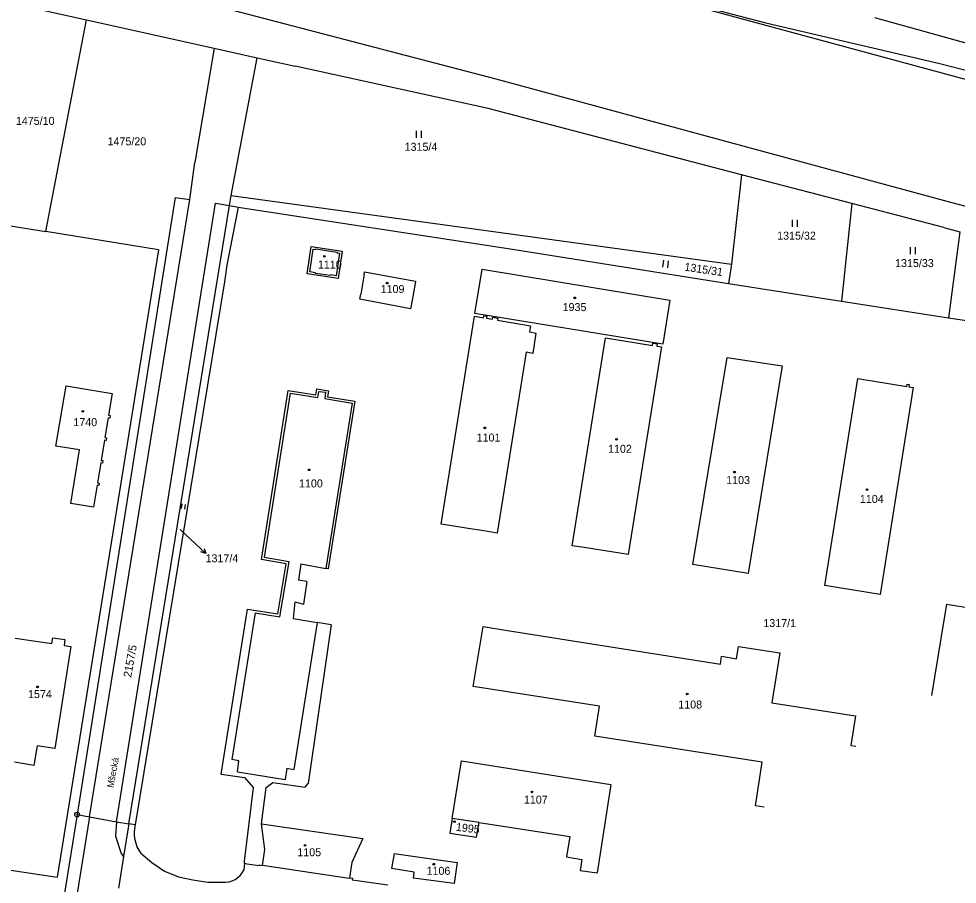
# Model space of a CAD drawing. Extents: x -779596 to -776743, y -1030330 to -1024513.
# Drawn here: x -778728.9 to -778529.6, y -1029872.1 to -1029688.2 of the extents above; entities that cross this region are included whole.
import ezdxf

# ---------------------------------------------------------------- set-up
doc = ezdxf.new("R2010")
doc.units = 0
for name, color, linetype in [('hranice parcel', 7, 'Continuous'), ('hranice vnitřní', 7, 'Continuous'), ('kultura', 7, 'Continuous'), ('Kód', 7, 'Continuous'), ('názvosloví', 7, 'Continuous'), ('č_ parcel šipka', 7, 'Continuous'), ('č_pacel stav_', 7, 'Continuous'), ('č_parcel poz_', 7, 'Continuous')]:
    doc.layers.add(name, color=color, linetype=linetype)

msp = doc.modelspace()

# ---------------------------------------------------------------- linework, layer by layer
at = {"layer": 'hranice parcel'}
for points in [[(-778728.82, -1029685.3), (-778714.47, -1029688.49)], [(-778723.12, -1029733.47), (-778714.47, -1029688.49)], [(-778714.47, -1029688.49), (-778687.4, -1029694.47)], [(-778547.21, -1029688.01), (-778525.04, -1029694.15)], [(-778687.4, -1029694.47), (-778691.45, -1029718.81)], [(-778687.4, -1029694.47), (-778678.25, -1029696.53)], [(-778683.75, -1029725.76), (-778678.25, -1029696.53)], [(-778678.25, -1029696.53), (-778670.2, -1029698.32)], [(-778629.23, -1029707.34), (-778670.2, -1029698.32)], [(-778575.41, -1029721.37), (-778629.23, -1029707.34)], [(-778692.58, -1029726.61), (-778691.45, -1029718.81)], [(-778575.41, -1029721.37), (-778577.55, -1029740.4)], [(-778552.03, -1029727.46), (-778575.41, -1029721.37)], [(-778695.65, -1029726.2), (-778716.48, -1029857.29)], [(-778695.65, -1029726.2), (-778692.58, -1029726.61)], [(-778684.15, -1029727.9), (-778683.75, -1029725.76)], [(-778683.75, -1029725.76), (-778577.55, -1029740.4)], [(-778705.49, -1029859.24), (-778684.15, -1029727.9)], [(-778682.29, -1029728.26), (-778684.67, -1029740.58)], [(-778684.15, -1029727.9), (-778682.29, -1029728.26)], [(-778682.29, -1029728.26), (-778624.95, -1029737.08)], [(-778552.03, -1029727.46), (-778554.23, -1029748.22)], [(-778532.46, -1029732.56), (-778552.03, -1029727.46)], [(-778739.16, -1029730.88), (-778723.12, -1029733.47)], [(-778699.18, -1029737.34), (-778723.12, -1029733.47)], [(-778532.46, -1029732.56), (-778529.06, -1029733.5)], [(-778529.06, -1029733.5), (-778531.48, -1029751.76)], [(-778699.18, -1029737.34), (-778720.7, -1029870.58)], [(-778667.67, -1029742.45), (-778666.78, -1029736.64)], [(-778666.78, -1029736.64), (-778660.19, -1029737.62)], [(-778660.19, -1029737.62), (-778661.03, -1029743.41)], [(-778624.95, -1029737.08), (-778585.37, -1029743.37)], [(-778577.55, -1029740.4), (-778578.22, -1029744.48)], [(-778684.67, -1029740.58), (-778685.17, -1029744.12)], [(-778661.03, -1029743.41), (-778667.67, -1029742.45)], [(-778655.57, -1029742.53), (-778655.48, -1029741.99)], [(-778655.48, -1029741.99), (-778644.64, -1029743.96)], [(-778632.01, -1029750.85), (-778630.51, -1029741.46)], [(-778630.51, -1029741.46), (-778590.64, -1029747.99)], [(-778685.17, -1029744.12), (-778704.18, -1029859.45)], [(-778655.57, -1029742.53), (-778656.27, -1029746.74)], [(-778644.64, -1029743.96), (-778644.74, -1029744.51)], [(-778585.37, -1029743.37), (-778578.22, -1029744.48)], [(-778578.22, -1029744.48), (-778554.23, -1029748.22)], [(-778644.74, -1029744.51), (-778645.48, -1029748.77)], [(-778656.45, -1029747.79), (-778656.27, -1029746.74)], [(-778645.67, -1029749.84), (-778656.45, -1029747.79)], [(-778590.64, -1029747.99), (-778592.14, -1029757.37)], [(-778554.23, -1029748.22), (-778531.48, -1029751.76)], [(-778645.48, -1029748.77), (-778645.67, -1029749.84)], [(-778639.2, -1029795.58), (-778632.11, -1029751.44)], [(-778632.11, -1029751.44), (-778630.17, -1029751.77)], [(-778592.14, -1029757.37), (-778632.01, -1029750.85)], [(-778630.17, -1029751.77), (-778630.1, -1029751.33)], [(-778630.1, -1029751.33), (-778629.51, -1029751.43)], [(-778629.51, -1029751.43), (-778629.58, -1029751.87)], [(-778629.58, -1029751.87), (-778628.28, -1029752.09)], [(-778628.28, -1029752.09), (-778628.21, -1029751.65)], [(-778628.21, -1029751.65), (-778627.13, -1029751.83)], [(-778627.13, -1029751.83), (-778627.2, -1029752.27)], [(-778627.2, -1029752.27), (-778620.25, -1029753.44)], [(-778531.48, -1029751.76), (-778515.73, -1029754.1)], [(-778620.25, -1029753.44), (-778620.46, -1029754.77)], [(-778620.46, -1029754.77), (-778619.06, -1029755)], [(-778619.06, -1029755), (-778619.76, -1029759.32)], [(-778611.37, -1029800.19), (-778604.27, -1029756.04)], [(-778604.27, -1029756.04), (-778594.31, -1029757.62)], [(-778592.41, -1029757.93), (-778599.46, -1029802.02)], [(-778594.31, -1029757.62), (-778594.24, -1029757.17)], [(-778594.24, -1029757.17), (-778593.31, -1029757.32)], [(-778593.31, -1029757.32), (-778593.38, -1029757.77)], [(-778593.38, -1029757.77), (-778592.41, -1029757.93)], [(-778621.15, -1029759.09), (-778627.27, -1029797.48)], [(-778619.76, -1029759.32), (-778621.15, -1029759.09)], [(-778585.79, -1029804.18), (-778578.5, -1029760.18)], [(-778578.5, -1029760.18), (-778566.79, -1029762)], [(-778566.79, -1029762), (-778574, -1029806.09)], [(-778721, -1029779.02), (-778718.79, -1029766.21)], [(-778718.79, -1029766.21), (-778709.02, -1029767.82)], [(-778557.75, -1029808.66), (-778550.73, -1029764.66)], [(-778550.73, -1029764.66), (-778540.36, -1029766.35)], [(-778540.36, -1029766.35), (-778540.28, -1029765.88)], [(-778540.28, -1029765.88), (-778539.84, -1029765.95)], [(-778539.84, -1029765.95), (-778539.92, -1029766.43)], [(-778709.02, -1029767.82), (-778709.78, -1029772.47)], [(-778677.35, -1029803.13), (-778671.68, -1029767.2)], [(-778671.68, -1029767.2), (-778665.8, -1029768.13)], [(-778665.8, -1029768.13), (-778665.6, -1029766.87)], [(-778665.6, -1029766.87), (-778663.13, -1029767.26)], [(-778663.13, -1029767.26), (-778663.33, -1029768.53)], [(-778538.98, -1029766.58), (-778545.96, -1029810.56)], [(-778539.92, -1029766.43), (-778538.98, -1029766.58)], [(-778663.33, -1029768.53), (-778657.52, -1029769.45)], [(-778657.52, -1029769.45), (-778663.16, -1029805.09)], [(-778709.87, -1029773.01), (-778710.56, -1029777.21)], [(-778709.52, -1029773.07), (-778709.87, -1029773.01)], [(-778709.78, -1029772.47), (-778709.44, -1029772.52)], [(-778709.44, -1029772.52), (-778709.52, -1029773.07)], [(-778710.65, -1029777.75), (-778711.35, -1029782.06)], [(-778710.3, -1029777.81), (-778710.65, -1029777.75)], [(-778710.56, -1029777.21), (-778710.21, -1029777.27)], [(-778710.21, -1029777.27), (-778710.3, -1029777.81)], [(-778715.97, -1029779.84), (-778721, -1029779.02)], [(-778717.82, -1029791.2), (-778715.97, -1029779.84)], [(-778711.35, -1029782.06), (-778711.01, -1029782.11)], [(-778711.01, -1029782.11), (-778711.1, -1029782.66)], [(-778711.44, -1029782.6), (-778712.13, -1029786.8)], [(-778711.1, -1029782.66), (-778711.44, -1029782.6)], [(-778712.22, -1029787.34), (-778712.98, -1029791.99)], [(-778711.87, -1029787.4), (-778712.22, -1029787.34)], [(-778712.13, -1029786.8), (-778711.78, -1029786.86)], [(-778711.78, -1029786.86), (-778711.87, -1029787.4)], [(-778712.98, -1029791.99), (-778717.82, -1029791.2)], [(-778632.57, -1029796.64), (-778639.2, -1029795.58)], [(-778630.54, -1029796.96), (-778632.57, -1029796.64)], [(-778627.27, -1029797.48), (-778630.54, -1029796.96)], [(-778608.84, -1029800.58), (-778611.37, -1029800.19)], [(-778599.46, -1029802.02), (-778608.84, -1029800.58)], [(-778672.06, -1029804.02), (-778677.35, -1029803.13)], [(-778673.87, -1029814.67), (-778672.06, -1029804.02)], [(-778668.97, -1029804.06), (-778669.5, -1029807.49)], [(-778668.97, -1029804.06), (-778663.65, -1029805.01)], [(-778574, -1029806.09), (-778585.79, -1029804.18)], [(-778663.16, -1029805.09), (-778663.65, -1029805.01)], [(-778667.68, -1029807.78), (-778669.5, -1029807.49)], [(-778667.68, -1029807.78), (-778668.39, -1029812.56)], [(-778545.96, -1029810.56), (-778557.75, -1029808.66)], [(-778670.26, -1029812.13), (-778670.62, -1029815.61)], [(-778670.26, -1029812.13), (-778668.39, -1029812.56)], [(-778685.9, -1029848.72), (-778680.28, -1029813.65)], [(-778680.28, -1029813.65), (-778673.87, -1029814.67)], [(-778531.93, -1029812.56), (-778533.12, -1029819.9)], [(-778531.93, -1029812.56), (-778510.985, -1029815.95)], [(-778670.62, -1029815.61), (-778665.53, -1029816.51)], [(-778662.52, -1029816.98), (-778667.44, -1029850.65)], [(-778662.52, -1029816.98), (-778665.53, -1029816.51)], [(-778632.41, -1029830.09), (-778630.3, -1029817.35)], [(-778630.3, -1029817.35), (-778625.11, -1029818.17)], [(-778625.11, -1029818.17), (-778579.91, -1029825.33)], [(-778729.63, -1029819.78), (-778721.82, -1029820.96)], [(-778721.82, -1029820.96), (-778721.64, -1029819.74)], [(-778721.64, -1029819.74), (-778719.06, -1029820.13)], [(-778719.06, -1029820.13), (-778719.24, -1029821.35)], [(-778533.12, -1029819.9), (-778535.077, -1029832.02)], [(-778717.81, -1029821.57), (-778721.22, -1029843.28)], [(-778719.24, -1029821.35), (-778717.81, -1029821.57)], [(-778576.46, -1029824.17), (-778576.09, -1029821.61)], [(-778576.09, -1029821.61), (-778567.32, -1029822.92)], [(-778579.91, -1029825.33), (-778579.69, -1029823.67)], [(-778579.69, -1029823.67), (-778576.46, -1029824.17)], [(-778567.32, -1029822.92), (-778568.98, -1029833.55)], [(-778605.58, -1029834.28), (-778632.41, -1029830.09)], [(-778568.98, -1029833.55), (-778551.21, -1029836.32)], [(-778606.56, -1029840.66), (-778605.58, -1029834.28)], [(-778551.21, -1029836.32), (-778552.19, -1029842.62)], [(-778571.01, -1029846.12), (-778606.56, -1029840.66)], [(-778724.99, -1029842.67), (-778725.66, -1029846.84)], [(-778721.22, -1029843.28), (-778724.99, -1029842.67)], [(-778552.19, -1029842.62), (-778551.186, -1029842.766)], [(-778636.83, -1029858.09), (-778634.86, -1029845.89)], [(-778634.86, -1029845.89), (-778603.18, -1029850.9)], [(-778725.66, -1029846.84), (-778729.79, -1029846.18)], [(-778572.46, -1029855.44), (-778571.01, -1029846.12)], [(-778685.9, -1029848.72), (-778680.96, -1029849.44)], [(-778680.96, -1029849.44), (-778679.05, -1029851.58)], [(-778680.92, -1029867.19), (-778679.05, -1029851.58)], [(-778677.34, -1029859.26), (-778676.33, -1029851.54)], [(-778676.33, -1029851.54), (-778674.91, -1029850.45)], [(-778674.91, -1029850.45), (-778668.03, -1029851.44)], [(-778668.03, -1029851.44), (-778667.44, -1029850.65)], [(-778603.18, -1029850.9), (-778606.06, -1029869.67)], [(-778570.603, -1029855.717), (-778572.46, -1029855.44)], [(-778716.48, -1029857.29), (-778719.14, -1029873.99)], [(-778716.48, -1029857.29), (-778713.86, -1029857.77)], [(-778713.86, -1029857.77), (-778708.13, -1029858.82)], [(-778708.13, -1029858.82), (-778705.49, -1029859.24)], [(-778705.49, -1029859.24), (-778706.61, -1029866.18)], [(-778704.18, -1029859.45), (-778705.49, -1029859.24)], [(-778676.6, -1029864.71), (-778677.34, -1029859.26)], [(-778677.34, -1029859.26), (-778655.83, -1029862.4)], [(-778636.83, -1029858.09), (-778637.34, -1029861.23)], [(-778631.15, -1029858.97), (-778636.83, -1029858.09)], [(-778631.66, -1029862.11), (-778631.15, -1029858.97)], [(-778631.15, -1029858.97), (-778611.85, -1029861.94)], [(-778637.34, -1029861.23), (-778631.66, -1029862.11)], [(-778611.85, -1029861.94), (-778612.55, -1029866.23)], [(-778655.83, -1029862.4), (-778658.18, -1029867.44)], [(-778702.97, -1029865.49), (-778700.58, -1029867.48)], [(-778677.15, -1029868.08), (-778676.6, -1029864.71)], [(-778649.2, -1029865.57), (-778649.74, -1029868.75)], [(-778649.2, -1029865.57), (-778635.77, -1029867.45)], [(-778747.94, -1029866.48), (-778720.7, -1029870.58)], [(-778706.61, -1029866.18), (-778707.7, -1029872.91)], [(-778700.58, -1029867.48), (-778697.96, -1029869.29)], [(-778680.96, -1029867.63), (-778681.09, -1029869.06)], [(-778680.96, -1029867.63), (-778680.92, -1029867.19)], [(-778680.96, -1029867.63), (-778680.39, -1029867.72)], [(-778680.39, -1029867.72), (-778678.86, -1029867.97)], [(-778678.86, -1029867.97), (-778677.85, -1029868.13)], [(-778677.85, -1029868.13), (-778677.83, -1029867.98)], [(-778677.83, -1029867.98), (-778677.15, -1029868.08)], [(-778658.18, -1029867.44), (-778658.67, -1029870.7)], [(-778635.77, -1029867.45), (-778636.41, -1029871.93)], [(-778612.55, -1029866.23), (-778609.29, -1029866.81)], [(-778609.29, -1029866.81), (-778609.67, -1029869.13)], [(-778697.96, -1029869.29), (-778694.96, -1029870.5)], [(-778658.69, -1029870.85), (-778677.15, -1029868.08)], [(-778644.95, -1029869.53), (-778649.74, -1029868.75)], [(-778645.07, -1029870.81), (-778644.95, -1029869.53)], [(-778609.67, -1029869.13), (-778606.06, -1029869.67)], [(-778694.96, -1029870.5), (-778691.88, -1029871.11)], [(-778691.88, -1029871.11), (-778688.76, -1029871.61)], [(-778688.76, -1029871.61), (-778685.59, -1029871.64)], [(-778658.67, -1029870.7), (-778658.69, -1029870.85)], [(-778658.67, -1029870.7), (-778658.02, -1029870.8)], [(-778658.02, -1029870.8), (-778658.06, -1029871.11)], [(-778658.06, -1029871.11), (-778657.02, -1029871.26)], [(-778657.02, -1029871.26), (-778650.5, -1029872.23)], [(-778636.41, -1029871.93), (-778645.07, -1029870.81)]]:
    msp.add_lwpolyline(points, dxfattribs=at)
for centre, radius, start, end in [((-778697.051, -1029861.163), 7.332, 166.49009, 216.16342), ((-778685.22, -1029867.071), 4.584, 265.37237, 334.29432)]:
    msp.add_arc(centre, radius, start, end, dxfattribs=at)
at = {"layer": 'hranice vnitřní'}
for points in [[(-778627.53, -1029701.07), (-778723.46, -1029675.95)], [(-778524.21, -1029702.16), (-778620.72, -1029675.97)], [(-778620.72, -1029675.97), (-778570.28, -1029689.09)], [(-778570.28, -1029689.09), (-778533.3, -1029697.77)], [(-778533.3, -1029697.77), (-778473.84, -1029713.1)], [(-778531.02, -1029727.25), (-778627.53, -1029701.07)], [(-778713.86, -1029857.77), (-778692.58, -1029726.61)], [(-778708.13, -1029858.82), (-778687.07, -1029727.43)], [(-778687.07, -1029727.43), (-778684.15, -1029727.9)], [(-778418.674, -1029756.762), (-778531.02, -1029727.25)], [(-778667.1, -1029742.03), (-778666.36, -1029737.2)], [(-778666.36, -1029737.2), (-778665.79, -1029737.29)], [(-778665.79, -1029737.29), (-778665.77, -1029737.14)], [(-778665.77, -1029737.14), (-778661.29, -1029737.81)], [(-778660.75, -1029738.04), (-778661.45, -1029742.84)], [(-778661.29, -1029737.81), (-778661.31, -1029737.96)], [(-778661.31, -1029737.96), (-778660.75, -1029738.04)], [(-778665.86, -1029742.21), (-778667.1, -1029742.03)], [(-778665.88, -1029742.36), (-778665.86, -1029742.21)], [(-778662.71, -1029742.81), (-778665.88, -1029742.36)], [(-778662.69, -1029742.66), (-778662.71, -1029742.81)], [(-778661.45, -1029742.84), (-778662.69, -1029742.66)], [(-778671.26, -1029767.77), (-778676.78, -1029802.71)], [(-778671.26, -1029767.77), (-778665.39, -1029768.71)], [(-778665.39, -1029768.71), (-778665.18, -1029767.44)], [(-778665.18, -1029767.44), (-778663.71, -1029767.55)], [(-778663.71, -1029767.55), (-778663.9, -1029768.94)], [(-778663.9, -1029768.94), (-778658.09, -1029769.87)], [(-778658.09, -1029769.87), (-778663.65, -1029805.01)], [(-778671.48, -1029803.61), (-778676.78, -1029802.71)], [(-778673.46, -1029815.25), (-778671.48, -1029803.61)], [(-778678.66, -1029814.41), (-778683.6, -1029845.57)], [(-778678.66, -1029814.41), (-778673.46, -1029815.25)], [(-778665.53, -1029816.51), (-778670.49, -1029847.71)], [(-778682.14, -1029845.84), (-778683.6, -1029845.57)], [(-778682.46, -1029848.21), (-778682.14, -1029845.84)], [(-778671.94, -1029847.43), (-778672.33, -1029849.8)], [(-778671.94, -1029847.43), (-778670.49, -1029847.71)], [(-778682.46, -1029848.21), (-778672.33, -1029849.8)], [(-778713.86, -1029857.77), (-778716.06, -1029871.33)], [(-778708.13, -1029858.82), (-778708.36, -1029861.84)], [(-778708.36, -1029861.84), (-778707.13, -1029865.58)], [(-778707.13, -1029865.58), (-778706.61, -1029866.18)], [(-778716.06, -1029871.33), (-778721.88, -1029909)]]:
    msp.add_lwpolyline(points, dxfattribs=at)
at = {"layer": 'kultura'}
for points in [[(-778644.427, -1029713.565), (-778644.427, -1029712.065)], [(-778643.393, -1029713.565), (-778643.393, -1029712.065)], [(-778564.587, -1029732.435), (-778564.587, -1029730.935)], [(-778563.553, -1029732.435), (-778563.553, -1029730.935)], [(-778539.547, -1029738.265), (-778539.547, -1029736.765)], [(-778538.513, -1029738.265), (-778538.513, -1029736.765)], [(-778592.107, -1029741.028), (-778591.937, -1029739.538)], [(-778591.08, -1029741.146), (-778590.91, -1029739.655)], [(-778694.318, -1029792.283), (-778694.17, -1029791.289)], [(-778693.634, -1029792.385), (-778693.486, -1029791.391)]]:
    msp.add_lwpolyline(points, dxfattribs=at)
for centre in [(-778664.01, -1029738.71), (-778650.64, -1029744.4), (-778610.81, -1029747.54), (-778715.28, -1029771.65), (-778629.91, -1029775.15), (-778601.95, -1029777.59), (-778667.21, -1029784.06), (-778576.93, -1029784.54), (-778548.8, -1029788.24), (-778724.9, -1029830.16), (-778586.95, -1029831.66), (-778619.9, -1029852.46), (-778636.36, -1029858.78), (-778668.08, -1029863.83), (-778640.75, -1029867.83)]:
    msp.add_circle(centre, 0.175, dxfattribs=at)
at = {"layer": 'Kód'}
for radius in [0.5, 0.032]:
    msp.add_circle((-778716.48, -1029857.29), radius, dxfattribs=at)
at = {"layer": 'č_ parcel šipka'}
for points in [[(-778694.62, -1029796.71), (-778691.32, -1029799.76)], [(-778691.32, -1029799.76), (-778689.119, -1029801.798)], [(-778689.513, -1029800.752), (-778689.119, -1029801.798), (-778690.193, -1029801.485)]]:
    msp.add_lwpolyline(points, dxfattribs=at)

# ---------------------------------------------------------------- texts
at = {"layer": 'názvosloví'}
msp.add_text('Mšecká', height=1.4, rotation=79.60063, dxfattribs=at).set_placement((-778708.77, -1029851.658))
at = {"layer": 'č_ parcel šipka'}
msp.add_text('1317/4', height=1.7, dxfattribs=at).set_placement((-778689.21, -1029803.7))
at = {"layer": 'č_pacel stav_'}
for s, p in [('1110', (-778665.36, -1029741.31)), ('1109', (-778652.04, -1029746.51)), ('1935', (-778613.41, -1029750.34)), ('1740', (-778717.28, -1029774.78)), ('1101', (-778631.66, -1029778.05)), ('1102', (-778603.76, -1029780.44)), ('1100', (-778669.37, -1029787.8)), ('1103', (-778578.68, -1029787.09)), ('1104', (-778550.3, -1029791.09)), ('1574', (-778726.9, -1029832.54)), ('1108', (-778588.85, -1029834.76)), ('1107', (-778621.63, -1029854.97)), ('1105', (-778669.73, -1029866.13)), ('1106', (-778642.29, -1029870.08))]:
    msp.add_text(s, height=1.7, dxfattribs=at).set_placement(p)
msp.add_text('1995', height=1.7, rotation=352.90281, dxfattribs=at).set_placement((-778636.137, -1029860.707))
at = {"layer": 'č_parcel poz_'}
for s, height, p in [('1475/10', 1.7, (-778729.48, -1029710.79)), ('1475/20', 1.7, (-778710.02, -1029715.13)), ('1315/4', 1.7, (-778646.95, -1029716.3)), ('1315/32', 1.7, (-778567.86, -1029735.17)), ('1315/33', 1.7, (-778542.83, -1029741)), ('1317/4', 0.1, (-778694.619, -1029796.51)), ('1317/1', 1.7, (-778570.8, -1029817.46))]:
    msp.add_text(s, height=height, dxfattribs=at).set_placement(p)
for s, rotation, p in [('1315/31', 351.6028, (-778587.633, -1029741.732)), ('2157/5', 79.80063, (-778705.011, -1029828.248))]:
    msp.add_text(s, height=1.7, rotation=rotation, dxfattribs=at).set_placement(p)

doc.saveas('drawing.dxf')
